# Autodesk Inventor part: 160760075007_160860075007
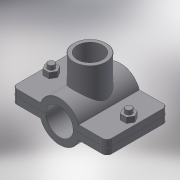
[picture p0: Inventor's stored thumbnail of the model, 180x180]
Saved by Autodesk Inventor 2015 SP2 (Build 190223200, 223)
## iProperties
Created: 2017-05
Part Number: 160760075007_160860075007
Material: Generic
Description: PLASSON SADDLE 75-3/4"
Document SubType Name: Modeling
Designer: KIM
Density: 1 g/cm^3
Appearance: Default
Author: KIM
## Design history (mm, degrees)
derived "16076.ipt"
feature "Solid1::16076.ipt"
feature "Solid2::16076.ipt"
tag "TaggingFeature1"
body "Solid1"
other parameters: "d0" = 93.75, "d1" = 122, "d2" = 37.5, "d3" = 75, "d4" = 98, "d5" = 0, "d6" = 6.1, "d7" = 122, "d8" = 0.1, "d10" = 0, "d11" = 0.75, "d14" = 31.3521, "d20" = 0.75, "d23" = 0.75, "d37" = 8, "d38" = 45.5, "d39" = 0, "d40" = 3, "d41" = 5, "d42" = 0, "d43" = 6, "d44" = 3, "d45" = 0, "d46" = 0.75, "d51" = 65, "d52" = 24.117, "d53" = 19, "d54" = 0, "d57" = 0, "d58" = 81, "d60" = 0, "d63" = 8, "d66" = 82, "d_" = 75, "G_" = 24.117, "A_" = 65, "L_" = 122, "L_1" = 98, "l_2" = 19
